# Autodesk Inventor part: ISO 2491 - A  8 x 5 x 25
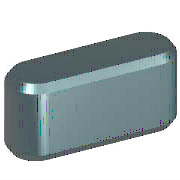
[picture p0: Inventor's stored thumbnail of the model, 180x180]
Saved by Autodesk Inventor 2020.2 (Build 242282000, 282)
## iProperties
Manager: www.cadconsulting.pl
Company: Fabian Stasiak CAD Consulting
IsCustomPart: 0
Created: 2010-02
Part Number: ISO 2491 - A  8 x 5 x 25
Material: Stal, miękka
Description: Wpusty pryzmatyczne cienkie
Document SubType Name: Modeling
Standard: ISO 2491
Designer: F.Stasiak
Standard Revision: First edition 1974-08-15
Standards Organization: ISO
Language: pl-PL
Size Designation: A  8 x 5 x 25
Categories: <MemberInstance><Categories><Category DisplayName="Części wałów" InternalName="7f7aeb1f-a693-4053-b835-cee3144e0d98" Mnemonic="SHFT"><Category DisplayName="Klin
Density: 1 g/cm^3
Appearance: Metal-Stal
Author: F.Stasiak
Subject: Zbiór ćwiczeń. Autodesk Inventor 2020. Kurs podstawowy
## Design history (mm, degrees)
sketch "Sketch1"
  geometry: L1 (4, 4)-(21, 4); L2 (21, -4)-(4, -4); L3 (0, 9.4)-(0, -7.4) reference; L4 (-5, 0)-(30, 0) reference; L5 (25, 0)-(25, 7); A1 r 4 centre (4, 0) between (4, 4) and (4, -4); A2 r 4 centre (21, 0) between (21, -4) and (21, 4)
  constraints: 6 end point, 5 point on circle, 4 tangent, 3 point on line, 2 centre point, 1 horizontal, 1 parallel, 1 perpendicular
  dimensions: "d0" = 4 radius of A1 (= 0.5 x PB); "d13" = 4 radius of A2 (= 0.5 x PB); "d14" = 25 distance between parallel lines of L5 L3 (= NLG)
workplane "Work Plane1"
workplane "Work Plane2"
extrude "Body1" new body sketch "Sketch1" taper "d3" = 0 deg; stored distance "d4" = 10
chamfer "Chamfer1" distance "d8" = 0.4 (= PHH); stored, may be unused: second distance "d9" = 0.4 (= PHH), angle "d15" = 45 deg
workplane "Work Plane3"
body "Solid1"
other parameters: "d1" = -3 (= -PNT), "d2" = 2 (= PH - PNT), "NLG" = 25 [user parameter; used in 1 equation term], "PB" = 8 [user parameter; used in 2 equation terms], "PNT" = 3 [user parameter; used in 2 equation terms], "PH" = 5 [user parameter; used in 1 equation term], "PHH" = 0.4 [user parameter; used in 2 equation terms], "d10" = 0, "d16" = 0, "d17" = 0, "d18" = 0, "RR" = 0.16 [user parameter], "WDMIN" = 22 [user parameter], "PLB1" = 25 [user parameter], "PLB2" = 25 [user parameter], "PUEB" = 2.3 [user parameter]
